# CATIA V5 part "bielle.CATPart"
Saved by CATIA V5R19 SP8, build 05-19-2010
Part number: bielle
Bounding box of the stored display mesh (mm): x -16 to 2, y -2.957 to 41.957, z -36.999 to -9.001
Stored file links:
  C:\Users\rcousturie\Desktop\EU_thinkMotion\iao\IAO_MMS_Groupe1\glenerrant\glenerrant\Nouveau dossier\bielle.CATPart
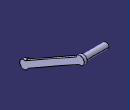
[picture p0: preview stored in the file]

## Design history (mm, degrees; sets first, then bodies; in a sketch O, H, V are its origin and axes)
Set1
  Point1: (0, 39, -12)
  Point2: (0, 0, -34)
Body1 (main body)
  Line1: stored without definition
  Line2: stored without definition
  Sketch1 on yz-plane, origin (0, 0, 0), H (0, 1, 0), V (0, 0, 1)
    arc A1 centre (39, -12) radius 3 from (38.0351, -14.8406) to (36.0698, -11.3567) ccw
    point P1 (39, -12)
    arc A2 centre (0, -34) radius 3 from (0.9649, -31.1594) to (2.9302, -34.6433) ccw
    point P2 (0, -34)
    reference projected point E1 (39, -12) from Point1
    reference projected point E2 (0, -34) from Point2
    line L1 (0.9649, -31.1594) -> (36.0698, -11.3567)
    line L2 (38.0351, -14.8406) -> (2.9302, -34.6433)
    point P5 (38.0351, -14.8406)
    reference projected line E3 (0, -34) -> (39, -12) from Line1
    reference projected line E4 (0, -34) -> (39, -12) from Line1
    point P7 (38.0351, -14.8406)
    reference projected line E5 (0, -34) -> (39, -12) from Line2
    radius A1 = 3
    radius A2 = 3
    distance L1 E5 = 2
    coincidence: P1 E1, P2 E2, P5 A1, L2 P7, P5 P7
    symmetry: L2 L1 E3
    parallelism: L2 L1, L1 E4
  Pad1: profile Sketch1, direction (1, 0, 0), length 2
  Sketch2 on start face of Pad1, origin (0, 0, 0), H (0, -1, 0), V (0, 0, 1)
    circle A1 centre (0, -34) radius 2
    point P1 (0, -34)
    reference projected point E1 (0, -34) from Point2
    radius A1 = 2
    coincidence: P1 E1
  Pad2: profile Sketch2, direction (-1, 0, 0), length 2
  Sketch3 on start face of Pad1, origin (0, 0, 0), H (0, -1, 0), V (0, 0, 1)
    circle A1 centre (-39, -12) radius 2
    point P1 (-39, -12)
    reference projected point E1 (-39, -12) from Point1
    radius A1 = 2
    coincidence: P1 E1
  Pad3: profile Sketch3, direction (-1, 0, 0), length 16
